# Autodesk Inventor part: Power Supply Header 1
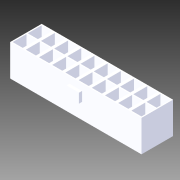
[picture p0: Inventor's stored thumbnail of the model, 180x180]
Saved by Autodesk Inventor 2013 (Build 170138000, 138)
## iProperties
Company: Autodesk Inc.
Created: 2005-12
Part Number: Power Supply Header 1
Document SubType Name: Modeling
Designer: Autodesk Inc.
Density: 1 g/cm^3
Mass: 2.2042 g
Surface Area: 40.0736 cm^2
Volume: 2.2042 cm^3
Material: Allgemein
Title: Personal Computer
Author: Autodesk Inc.
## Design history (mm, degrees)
sketch "Sketch1"
  geometry: L1 (0, 7)-(0, -7) reference; L2 (-29.144, 0)-(29.144, 0) reference; L3 (-20.817, 5)-(20.817, 5); L4 (20.817, 5)-(20.817, -5); L5 (20.817, -5)-(-20.817, -5); L6 (-20.817, -5)-(-20.817, 5)
  constraints: 8 end point, 2 parallel, 1 horizontal, 1 perpendicular, 2 other
  dimensions: "d0" = 41.634 distance of L3.start L3.end; "d1" = 10 distance of L5.end L3.start
extrude "Extrusion1" new body sketch "Sketch1" distance "d2" = 10; taper "d3" = 0 deg
sketch "Sketch5"
  geometry: L1 (41.634, 10)-(0, 10); L2 (18.817, 8)-(22.817, 8); L3 (22.817, 8)-(22.817, 5); L4 (22.817, 5)-(18.817, 5); L5 (18.817, 5)-(18.817, 8); 2 further points
  constraints: 10 end point, 2 midpoint, 2 parallel, 1 horizontal, 1 perpendicular, 1 vertical alignment
  dimensions: "d20" = 4 distance of L3.end L4.end; "d21" = 3 distance of L2.end L3.end; "d22" = 2 distance between parallel lines of L1 L2
extrude "Extrusion5" join sketch "Sketch5" distance "d23" = 1; taper "d24" = 0 deg
workplane "Work Plane1"
sketch "Sketch11"
  geometry: L1 (-17.217, -4.6)-(-20.417, -4.6); L2 (-20.417, -4.6)-(-20.417, -0.2); L3 (-20.417, -0.2)-(-17.217, -0.2); L4 (-17.217, -0.2)-(-17.217, -4.6)
  constraints: 8 end point, 2 parallel, 1 horizontal, 1 perpendicular
extrude "Extrusion11" cut sketch "Sketch11" distance "d49" = 7; taper "d50" = 0 deg
body "Solid1"
pattern_linear "Rectangular Pattern3" dims "d53" = 4.182, "d56" = 4.8
other parameters: "d4" = 0
